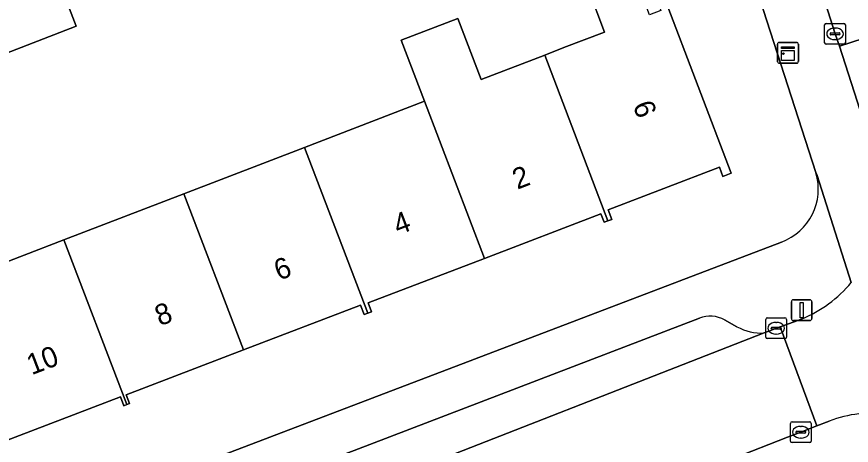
# Model space of a CAD drawing. Extents: x 159262 to 160143, y 383399 to 384319.
# Drawn here: x 159394.93 to 159435.12, y 383849.77 to 383870.4 of the extents above; entities that cross this region are included whole.
import ezdxf

# ---------------------------------------------------------------- set-up
doc = ezdxf.new("R2010")
doc.units = 0
for name, color, linetype in [('IMGEO_Erf', 7, 'Continuous'), ('IMGEO_Kast', 7, 'Continuous'), ('IMGEO_Kolk', 7, 'Continuous'), ('IMGEO_Lichtmast', 7, 'Continuous'), ('IMGEO_Pand', 7, 'Continuous'), ('IMGEO_Pand_nummerreeks', 7, 'Continuous'), ('IMGEO_Parkeervlak_open', 7, 'Continuous'), ('IMGEO_Rijbaan_lokaal_gesloten', 7, 'Continuous'), ('IMGEO_Rijbaan_lokaal_open', 7, 'Continuous'), ('IMGEO_Voetpad_open', 7, 'Continuous')]:
    doc.layers.add(name, color=color, linetype=linetype)

msp = doc.modelspace()

# ---------------------------------------------------------------- linework, layer by layer
at = {"layer": 'IMGEO_Erf'}
for points in [[(159433.414, 383862.892), (159427.008, 383882.725), (159397.222, 383871.414), (159397.789, 383869.946), (159393.849, 383868.425)], [(159391.45, 383857.448), (159397.196, 383859.656), (159402.972, 383861.875), (159408.786, 383864.109), (159414.57, 383866.331), (159413.447, 383869.273), (159416.17, 383870.319), (159417.293, 383867.378), (159420.353, 383868.553), (159421.277, 383868.908), (159423.238, 383869.661), (159422.439, 383871.755)], [(159426.149, 383871.221), (159429.341, 383862.867), (159428.935, 383862.712), (159428.766, 383863.153), (159423.405, 383861.104), (159423.581, 383860.644), (159423.398, 383860.574), (159423.217, 383860.504), (159423.063, 383860.907), (159417.458, 383858.766), (159411.848, 383856.623), (159412.012, 383856.195), (159411.832, 383856.126), (159411.657, 383856.059), (159411.484, 383856.513), (159405.841, 383854.357), (159400.197, 383852.2), (159400.357, 383851.779), (159400.222, 383851.728), (159400.088, 383851.677), (159399.926, 383852.101), (159394.31, 383849.955)], [(159369.194, 383835.764), (159370.416, 383836.226), (159382.457, 383840.783), (159431.75, 383859.554)]]:
    msp.add_lwpolyline(points, dxfattribs=at)
msp.add_arc((159430.812, 383862.105), 2.718, 290.1854, 16.8219, dxfattribs=at)
at = {"layer": 'IMGEO_Kast'}
for p, q in [((159431.643, 383869.157), (159432.484, 383869.157)), ((159432.484, 383869.157), (159431.643, 383869.157)), ((159431.568, 383868.232), (159431.568, 383869.073)), ((159431.568, 383869.073), (159431.568, 383868.232)), ((159432.568, 383869.082), (159432.568, 383868.241)), ((159432.568, 383868.241), (159432.568, 383869.082)), ((159432.493, 383868.157), (159431.652, 383868.157)), ((159431.652, 383868.157), (159432.493, 383868.157))]:
    msp.add_line(p, q, dxfattribs=at)
for points in [[(159431.763, 383868.947), (159432.363, 383868.947), (159432.363, 383868.862), (159431.763, 383868.862), (159431.763, 383868.947)], [(159431.763, 383868.772), (159432.363, 383868.772), (159432.363, 383868.283), (159431.763, 383868.283), (159431.763, 383868.772)]]:
    msp.add_lwpolyline(points, dxfattribs=at)
msp.add_circle((159431.847, 383868.621), 0.0377, dxfattribs=at)
for centre, start, end in [((159431.646, 383869.079), 92.4484, 184.2845), ((159431.646, 383869.079), 92.4484, 184.2845), ((159432.49, 383869.079), 2.4484, 94.2845), ((159432.49, 383869.079), 2.4484, 94.2845), ((159431.646, 383868.235), 182.4484, 274.2845), ((159431.646, 383868.235), 182.4484, 274.2845), ((159432.49, 383868.235), 272.4484, 4.2845), ((159432.49, 383868.235), 272.4484, 4.2845)]:
    msp.add_arc(centre, 0.0779, start, end, dxfattribs=at)
at = {"layer": 'IMGEO_Kolk'}
for p, q in [((159433.835, 383869.147), (159433.835, 383869.999)), ((159433.91, 383870.073), (159434.762, 383870.073)), ((159434.836, 383869.999), (159434.836, 383869.147)), ((159434.094, 383869.567), (159434.094, 383869.579)), ((159434.137, 383869.616), (159434.535, 383869.616)), ((159434.323, 383869.853), (159434.348, 383869.853)), ((159434.578, 383869.579), (159434.578, 383869.567)), ((159434.532, 383869.53), (159434.134, 383869.53)), ((159434.346, 383869.293), (159434.321, 383869.293)), ((159434.762, 383869.073), (159433.91, 383869.073)), ((159431.072, 383855.905), (159431.924, 383855.905)), ((159430.997, 383854.979), (159430.997, 383855.831)), ((159431.485, 383855.685), (159431.51, 383855.685)), ((159431.998, 383855.831), (159431.998, 383854.979)), ((159431.256, 383855.399), (159431.256, 383855.411)), ((159431.694, 383855.362), (159431.296, 383855.362)), ((159431.299, 383855.448), (159431.697, 383855.448)), ((159431.508, 383855.125), (159431.483, 383855.125)), ((159431.74, 383855.411), (159431.74, 383855.399)), ((159431.924, 383854.905), (159431.072, 383854.905)), ((159432.189, 383849.975), (159432.189, 383850.827)), ((159432.264, 383850.901), (159433.116, 383850.901)), ((159432.677, 383850.681), (159432.702, 383850.681)), ((159433.19, 383850.827), (159433.19, 383849.975)), ((159432.448, 383850.395), (159432.448, 383850.407)), ((159432.886, 383850.358), (159432.488, 383850.358)), ((159432.491, 383850.444), (159432.889, 383850.444)), ((159432.932, 383850.407), (159432.932, 383850.395)), ((159433.116, 383849.901), (159432.264, 383849.901)), ((159432.7, 383850.121), (159432.675, 383850.121))]:
    msp.add_line(p, q, dxfattribs=at)
for points in [[(159433.835, 383869.147), (159433.835, 383869.999)], [(159433.91, 383870.073), (159434.762, 383870.073)], [(159434.836, 383869.999), (159434.836, 383869.147)], [(159434.762, 383869.073), (159433.91, 383869.073)], [(159431.072, 383855.905), (159431.924, 383855.905)], [(159430.997, 383854.979), (159430.997, 383855.831)], [(159431.998, 383855.831), (159431.998, 383854.979)], [(159431.924, 383854.905), (159431.072, 383854.905)], [(159432.189, 383849.975), (159432.189, 383850.827)], [(159432.264, 383850.901), (159433.116, 383850.901)], [(159433.19, 383850.827), (159433.19, 383849.975)], [(159433.116, 383849.901), (159432.264, 383849.901)]]:
    msp.add_lwpolyline(points, dxfattribs=at)
for centre, radius, start, end in [((159433.912, 383869.997), 0.0765, 91.552, 178.448), ((159433.912, 383869.997), 0.0765, 91.552, 178.448), ((159434.76, 383869.997), 0.0765, 1.552, 88.448), ((159434.76, 383869.997), 0.0765, 1.552, 88.448), ((159434.134, 383869.576), 0.0403, 85.8775, 175.7526), ((159434.131, 383869.566), 0.0366, 178.938, 274.7102), ((159434.535, 383869.573), 0.043, 264.8664, 352.4533), ((159434.539, 383869.578), 0.0386, 1.7309, 96.639), ((159433.912, 383869.149), 0.0765, 181.552, 268.448), ((159433.912, 383869.149), 0.0765, 181.552, 268.448), ((159434.76, 383869.149), 0.0765, 271.552, 358.448), ((159434.76, 383869.149), 0.0765, 271.552, 358.448), ((159431.074, 383855.829), 0.0765, 91.552, 178.448), ((159431.074, 383855.829), 0.0765, 91.552, 178.448), ((159431.922, 383855.829), 0.0765, 1.552, 88.448), ((159431.922, 383855.829), 0.0765, 1.552, 88.448), ((159431.296, 383855.408), 0.0403, 85.8775, 175.7526), ((159431.293, 383855.398), 0.0366, 178.938, 274.7102), ((159431.697, 383855.405), 0.043, 264.8664, 352.4533), ((159431.701, 383855.41), 0.0386, 1.7309, 96.639), ((159431.074, 383854.981), 0.0765, 181.552, 268.448), ((159431.074, 383854.981), 0.0765, 181.552, 268.448), ((159431.922, 383854.981), 0.0765, 271.552, 358.448), ((159431.922, 383854.981), 0.0765, 271.552, 358.448), ((159432.266, 383850.825), 0.0765, 91.552, 178.448), ((159432.266, 383850.825), 0.0765, 91.552, 178.448), ((159433.114, 383850.825), 0.0765, 1.552, 88.448), ((159433.114, 383850.825), 0.0765, 1.552, 88.448), ((159432.488, 383850.404), 0.0403, 85.8775, 175.7526), ((159432.485, 383850.394), 0.0366, 178.938, 274.7102), ((159432.889, 383850.401), 0.043, 264.8664, 352.4533), ((159432.893, 383850.406), 0.0386, 1.7309, 96.639), ((159432.266, 383849.977), 0.0765, 181.552, 268.448), ((159432.266, 383849.977), 0.0765, 181.552, 268.448), ((159433.114, 383849.977), 0.0765, 271.552, 358.448), ((159433.114, 383849.977), 0.0765, 271.552, 358.448)]:
    msp.add_arc(centre, radius, start, end, dxfattribs=at)
for centre, major_axis, ratio, start_param, end_param in [((159434.322, 383869.573), (-0.387, 0.002), 0.722429, 4.712389, 7.853982), ((159434.347, 383869.573), (-0.39, 0.002), 0.717154, 1.570796, 4.712389), ((159431.484, 383855.405), (-0.387, 0.002), 0.722429, 4.712389, 7.853982), ((159431.509, 383855.405), (-0.39, 0.002), 0.717154, 1.570796, 4.712389), ((159432.676, 383850.401), (-0.387, 0.002), 0.722429, 4.712389, 7.853982), ((159432.701, 383850.401), (-0.39, 0.002), 0.717154, 1.570796, 4.712389)]:
    msp.add_ellipse(centre, major_axis=major_axis, ratio=ratio, start_param=start_param, end_param=end_param, dxfattribs=at)
at = {"layer": 'IMGEO_Lichtmast'}
for p, q in [((159432.332, 383856.772), (159433.122, 383856.772)), ((159433.122, 383856.772), (159432.332, 383856.772)), ((159432.232, 383855.872), (159432.232, 383856.672)), ((159432.232, 383856.672), (159432.232, 383855.872)), ((159433.222, 383856.672), (159433.222, 383855.872)), ((159433.222, 383855.872), (159433.222, 383856.672)), ((159433.122, 383855.772), (159432.332, 383855.772)), ((159432.332, 383855.772), (159433.122, 383855.772))]:
    msp.add_line(p, q, dxfattribs=at)
msp.add_lwpolyline([(159432.652, 383856.647), (159432.802, 383856.647), (159432.802, 383855.897), (159432.652, 383855.897), (159432.652, 383856.647)], dxfattribs=at)
for centre, start, end in [((159432.332, 383856.672), 90, 180), ((159432.332, 383856.672), 90, 180), ((159433.122, 383856.672), 0, 90), ((159433.122, 383856.672), 360, 90), ((159432.332, 383855.872), 180, 270), ((159432.332, 383855.872), 180, 270), ((159433.122, 383855.872), 270, 0), ((159433.122, 383855.872), 270, 0)]:
    msp.add_arc(centre, 0.1, start, end, dxfattribs=at)
at = {"layer": 'IMGEO_Pand'}
for points in [[(159396.776, 383872.57), (159395.894, 383874.856), (159391.972, 383873.342), (159393.849, 383868.425), (159397.789, 383869.946), (159397.222, 383871.414)], [(159426.149, 383871.221), (159425.797, 383871.087), (159425.944, 383870.701), (159425.406, 383870.494), (159424.606, 383872.587), (159422.439, 383871.755), (159423.238, 383869.661), (159421.277, 383868.908), (159420.353, 383868.553), (159423.398, 383860.574), (159423.581, 383860.644), (159423.405, 383861.104), (159428.766, 383863.153), (159428.935, 383862.712), (159429.341, 383862.867)], [(159420.353, 383868.553), (159417.293, 383867.378), (159416.17, 383870.319), (159413.447, 383869.273), (159414.57, 383866.331), (159417.458, 383858.766), (159423.063, 383860.907), (159423.217, 383860.504), (159423.398, 383860.574)], [(159408.786, 383864.109), (159411.832, 383856.126), (159412.012, 383856.195), (159411.848, 383856.623), (159417.458, 383858.766), (159414.57, 383866.331)], [(159402.972, 383861.875), (159405.841, 383854.357), (159411.484, 383856.513), (159411.657, 383856.059), (159411.832, 383856.126), (159408.786, 383864.109)], [(159405.841, 383854.357), (159402.972, 383861.875), (159397.196, 383859.656), (159400.222, 383851.728), (159400.357, 383851.779), (159400.197, 383852.2)], [(159391.45, 383857.448), (159394.31, 383849.955), (159399.926, 383852.101), (159400.088, 383851.677), (159400.222, 383851.728), (159397.196, 383859.656)]]:
    msp.add_lwpolyline(points, close=True, dxfattribs=at)
at = {"layer": 'IMGEO_Parkeervlak_open'}
for points in [[(159427.802, 383855.889), (159411.178, 383849.519), (159383.074, 383838.931), (159374.2, 383835.498)], [(159429.612, 383855.479), (159429.019, 383855.805)], [(159371.844, 383832.486), (159383.623, 383837.11), (159411.861, 383847.734), (159430.92, 383855.178)]]:
    msp.add_lwpolyline(points, dxfattribs=at)
for centre, radius, start, end in [((159428.32, 383854.533), 1.452, 61.2103, 110.8929), ((159430.793, 383857.62), 2.446, 241.1138, 272.9674)]:
    msp.add_arc(centre, radius, start, end, dxfattribs=at)
at = {"layer": 'IMGEO_Rijbaan_lokaal_gesloten'}
msp.add_lwpolyline([(159435.282, 383890.861), (159434.439, 383890.605), (159428.205, 383888.576), (159428.257, 383888.427), (159429.908, 383883.667), (159430.052, 383883.216), (159431.145, 383879.803), (159433.052, 383873.612), (159434.337, 383869.573), (159434.544, 383868.974), (159442.124, 383871.452), (159440.61, 383876.155), (159439.532, 383879.49), (159437.664, 383885.207), (159436.231, 383889.666), (159435.934, 383890.56)], dxfattribs=at)
at = {"layer": 'IMGEO_Rijbaan_lokaal_open'}
for points in [[(159447.613, 383854.588), (159447.368, 383855.317), (159442.124, 383871.452), (159434.544, 383868.974), (159436.248, 383863.684)], [(159432.721, 383855.842), (159431.695, 383855.47), (159433.465, 383850.712), (159434.05, 383850.932)]]:
    msp.add_lwpolyline(points, dxfattribs=at)
msp.add_lwpolyline([(159432.041, 383850.161), (159432.689, 383850.402), (159433.465, 383850.712), (159431.695, 383855.47), (159431.498, 383855.404), (159431.28, 383855.319), (159430.92, 383855.178), (159411.861, 383847.734), (159383.623, 383837.11), (159371.844, 383832.486), (159373.65, 383827.758), (159377.676, 383829.295), (159387.324, 383832.951), (159404.16, 383839.368), (159413.728, 383842.98)], close=True, dxfattribs=at)
for centre, radius, start, end in [((159430.291, 383861.649), 6.295, 292.7114, 320.0899), ((159436.149, 383845.478), 5.844, 82.2038, 111.0503)]:
    msp.add_arc(centre, radius, start, end, dxfattribs=at)
at = {"layer": 'IMGEO_Voetpad_open'}
for points in [[(159421.273, 383900.478), (159426.589, 383884.021), (159427.008, 383882.725), (159433.414, 383862.892), (159433.479, 383862.754), (159435.119, 383857.61)], [(159436.248, 383863.684), (159434.544, 383868.974), (159434.337, 383869.573), (159433.052, 383873.612), (159431.145, 383879.803), (159430.67, 383879.65), (159429.578, 383883.063), (159430.052, 383883.216), (159429.908, 383883.667), (159429.432, 383883.515), (159427.896, 383888.312)], [(159435.119, 383857.61), (159433.479, 383862.754), (159433.414, 383862.892)], [(159431.75, 383859.554), (159382.457, 383840.783), (159370.416, 383836.226), (159371.844, 383832.486)], [(159374.2, 383835.498), (159383.074, 383838.931), (159411.178, 383849.519), (159427.802, 383855.889)], [(159429.019, 383855.805), (159429.612, 383855.479)], [(159430.92, 383855.178), (159431.28, 383855.319), (159431.498, 383855.404), (159431.695, 383855.47), (159432.721, 383855.842)], [(159434.05, 383850.932), (159433.465, 383850.712), (159432.689, 383850.402), (159432.041, 383850.161), (159413.728, 383842.98), (159404.16, 383839.368), (159387.324, 383832.951), (159377.676, 383829.295), (159373.65, 383827.758), (159374.358, 383825.902), (159387.616, 383830.972)]]:
    msp.add_lwpolyline(points, dxfattribs=at)
for centre, radius, start, end in [((159430.812, 383862.105), 2.718, 290.1854, 16.8219), ((159430.291, 383861.649), 6.295, 292.7114, 320.0899), ((159428.32, 383854.533), 1.452, 61.2103, 110.8929), ((159430.793, 383857.62), 2.446, 241.1138, 272.9674), ((159436.149, 383845.478), 5.844, 82.2038, 111.0503)]:
    msp.add_arc(centre, radius, start, end, dxfattribs=at)

# ---------------------------------------------------------------- texts
at = {"layer": 'IMGEO_Pand_nummerreeks'}
for s, rotation, p in [('6', 290.9127, (159424.583, 383866.131)), ('2', 20.89, (159419.034, 383862.068)), ('4', 20.8896, (159413.295, 383859.877)), ('6', 20.8896, (159407.554, 383857.686)), ('8', 20.8896, (159401.817, 383855.496)), ('10', 20.8896, (159395.645, 383853.14))]:
    msp.add_text(s, height=1, rotation=rotation, dxfattribs=at).set_placement(p)

doc.saveas('drawing.dxf')
